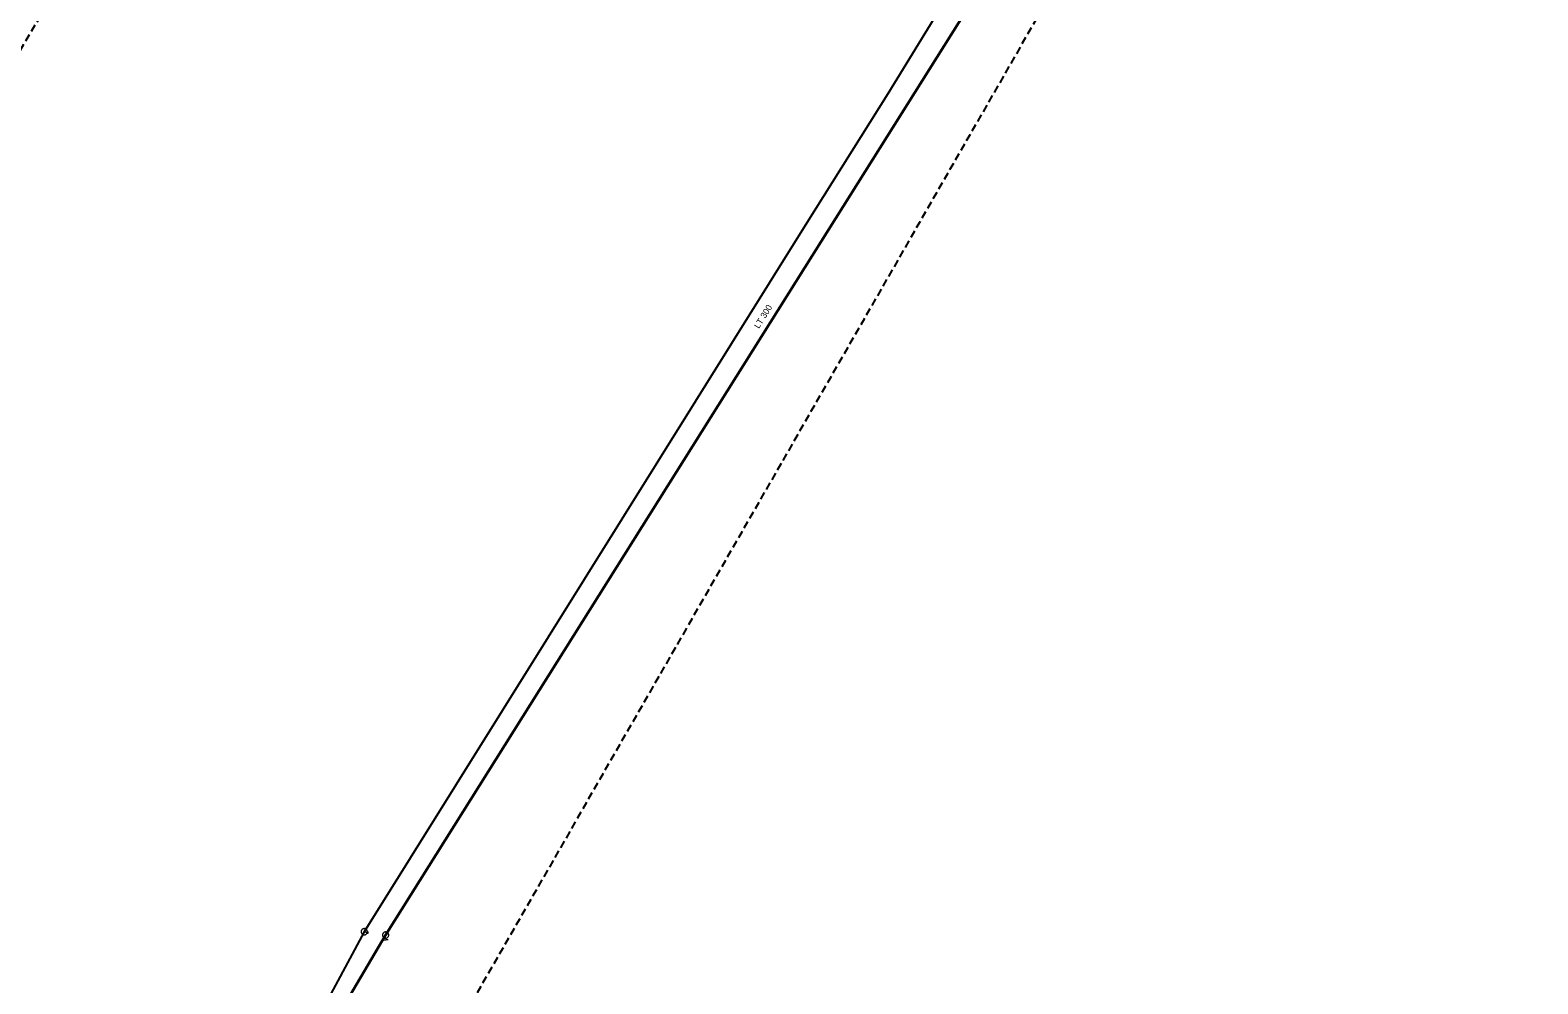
# Model space of a CAD drawing. Extents: x -724358 to -723714, y -973310 to -972026.
# Drawn here: x -724079.6 to -723836.6, y -972835.4 to -972681.7 of the extents above; entities that cross this region are included whole.
import ezdxf

# ---------------------------------------------------------------- set-up
doc = ezdxf.new("R2010")
doc.units = 0
doc.header["$LTSCALE"] = 0.4
doc.linetypes.add('MEDIUM_DASHED', pattern=[4.5, 3, -1.5])
for name, color, linetype, lineweight in [('1', 7, 'Continuous', 13), ('14', 7, 'Continuous', 13), ('17', 7, 'Continuous', 25), ('23', 7, 'Continuous', 13), ('47', 7, 'Continuous', 13), ('9', 7, 'Continuous', 13)]:
    doc.layers.add(name, color=color, linetype=linetype, lineweight=lineweight)

msp = doc.modelspace()

# ---------------------------------------------------------------- linework, layer by layer
at = {"layer": '1', "linetype": 'MEDIUM_DASHED', "lineweight": 25}
msp.add_lwpolyline([(-723809.944, -972026.35), (-723713.647, -972034.723), (-723734.581, -972361.295), (-724123.956, -973039.561), (-724241.187, -973309.611), (-724358.418, -973148.418), (-723860.186, -972315.24)], close=True, dxfattribs=at)
at = {"layer": '14'}
msp.add_line((-724025.8, -972827.022), (-724025.277, -972827.149), dxfattribs=at)
at = {"layer": '17', "lineweight": 35}
msp.add_line((-724070.768, -972909.289), (-724022.349, -972827.559), dxfattribs=at)
at = {"layer": '17'}
for points in [[(-723900.499, -972626.309), (-723922.64, -972661.32), (-723941.379, -972691.969), (-723954.71, -972713.199), (-723996.149, -972779.55), (-724025.8, -972827.022)], [(-724025.8, -972827.022), (-724033.14, -972840.629), (-724045.07, -972861.41), (-724063.359, -972892.16), (-724073.199, -972908.18)]]:
    msp.add_lwpolyline(points, dxfattribs=at)
at = {"layer": '17', "lineweight": 35}
msp.add_lwpolyline([(-724022.349, -972827.559), (-723952.142, -972715.728), (-723897.139, -972628.179)], dxfattribs=at)
at = {"layer": '23'}
for p in [(-724022.316, -972828.069), (-724022.639, -972828.37), (-724021.956, -972828.325)]:
    msp.add_line(p, (-724022.298, -972828.347), dxfattribs=at)
msp.add_lwpolyline([(-724022.844, -972827.587), (-724022.837, -972827.64), (-724022.828, -972827.691), (-724022.81, -972827.741), (-724022.788, -972827.787), (-724022.765, -972827.831), (-724022.732, -972827.874), (-724022.696, -972827.911), (-724022.658, -972827.947), (-724022.617, -972827.977), (-724022.57, -972828.001), (-724022.523, -972828.022), (-724022.474, -972828.037), (-724022.422, -972828.049), (-724022.371, -972828.055), (-724022.32, -972828.054), (-724022.269, -972828.048), (-724022.219, -972828.036), (-724022.169, -972828.02), (-724022.122, -972827.999), (-724022.076, -972827.972), (-724022.036, -972827.942), (-724021.996, -972827.907), (-724021.962, -972827.868), (-724021.932, -972827.824), (-724021.905, -972827.78), (-724021.884, -972827.734), (-724021.869, -972827.685), (-724021.858, -972827.633), (-724021.855, -972827.582), (-724021.852, -972827.527), (-724021.859, -972827.477), (-724021.871, -972827.426), (-724021.886, -972827.376), (-724021.908, -972827.33), (-724021.934, -972827.286), (-724021.964, -972827.243), (-724022, -972827.206), (-724022.038, -972827.17), (-724022.082, -972827.14), (-724022.126, -972827.115), (-724022.176, -972827.095), (-724022.225, -972827.077), (-724022.274, -972827.068), (-724022.328, -972827.063), (-724022.379, -972827.063), (-724022.43, -972827.069), (-724022.48, -972827.079), (-724022.53, -972827.097), (-724022.577, -972827.118), (-724022.623, -972827.145), (-724022.663, -972827.175), (-724022.703, -972827.211), (-724022.737, -972827.249), (-724022.767, -972827.29), (-724022.791, -972827.337), (-724022.815, -972827.383), (-724022.83, -972827.432), (-724022.838, -972827.484), (-724022.844, -972827.535)], close=True, dxfattribs=at)
at = {"layer": '47'}
for points in [[(-724025.3, -972827.022), (-724025.303, -972826.97), (-724025.311, -972826.918), (-724025.325, -972826.868), (-724025.343, -972826.819), (-724025.367, -972826.772), (-724025.396, -972826.728), (-724025.429, -972826.688), (-724025.466, -972826.651), (-724025.506, -972826.618), (-724025.55, -972826.589), (-724025.597, -972826.565), (-724025.646, -972826.547), (-724025.696, -972826.533), (-724025.748, -972826.525), (-724025.8, -972826.522), (-724025.852, -972826.525), (-724025.904, -972826.533), (-724025.955, -972826.547), (-724026.003, -972826.565), (-724026.05, -972826.589), (-724026.094, -972826.618), (-724026.135, -972826.651), (-724026.172, -972826.688), (-724026.205, -972826.728), (-724026.233, -972826.772), (-724026.257, -972826.819), (-724026.276, -972826.868), (-724026.289, -972826.918), (-724026.297, -972826.97), (-724026.3, -972827.022), (-724026.297, -972827.074), (-724026.289, -972827.126), (-724026.276, -972827.177), (-724026.257, -972827.225), (-724026.233, -972827.272), (-724026.205, -972827.316), (-724026.172, -972827.357), (-724026.135, -972827.394), (-724026.094, -972827.427), (-724026.05, -972827.455), (-724026.003, -972827.479), (-724025.955, -972827.498), (-724025.904, -972827.511), (-724025.852, -972827.519), (-724025.8, -972827.522), (-724025.748, -972827.519), (-724025.696, -972827.511), (-724025.646, -972827.498), (-724025.597, -972827.479), (-724025.55, -972827.455), (-724025.506, -972827.427), (-724025.466, -972827.394), (-724025.429, -972827.357), (-724025.396, -972827.316), (-724025.367, -972827.272), (-724025.343, -972827.225), (-724025.325, -972827.177), (-724025.311, -972827.126), (-724025.303, -972827.074)], [(-724025.718, -972827.022), (-724025.718, -972827.013), (-724025.72, -972827.005), (-724025.722, -972826.997), (-724025.725, -972826.989), (-724025.729, -972826.981), (-724025.734, -972826.974), (-724025.739, -972826.967), (-724025.745, -972826.961), (-724025.752, -972826.956), (-724025.759, -972826.951), (-724025.767, -972826.947), (-724025.775, -972826.944), (-724025.783, -972826.942), (-724025.791, -972826.94), (-724025.8, -972826.94), (-724025.809, -972826.94), (-724025.817, -972826.942), (-724025.825, -972826.944), (-724025.833, -972826.947), (-724025.841, -972826.951), (-724025.848, -972826.956), (-724025.855, -972826.961), (-724025.861, -972826.967), (-724025.867, -972826.974), (-724025.871, -972826.981), (-724025.875, -972826.989), (-724025.878, -972826.997), (-724025.88, -972827.005), (-724025.882, -972827.013), (-724025.882, -972827.022), (-724025.882, -972827.031), (-724025.88, -972827.039), (-724025.878, -972827.047), (-724025.875, -972827.055), (-724025.871, -972827.063), (-724025.867, -972827.07), (-724025.861, -972827.077), (-724025.855, -972827.083), (-724025.848, -972827.089), (-724025.841, -972827.093), (-724025.833, -972827.097), (-724025.825, -972827.1), (-724025.817, -972827.102), (-724025.809, -972827.104), (-724025.8, -972827.104), (-724025.791, -972827.104), (-724025.783, -972827.102), (-724025.775, -972827.1), (-724025.767, -972827.097), (-724025.759, -972827.093), (-724025.752, -972827.089), (-724025.745, -972827.083), (-724025.739, -972827.077), (-724025.734, -972827.07), (-724025.729, -972827.063), (-724025.725, -972827.055), (-724025.722, -972827.047), (-724025.72, -972827.039), (-724025.718, -972827.031)]]:
    msp.add_lwpolyline(points, close=True, dxfattribs=at)
at = {"layer": '9'}
for points in [[(-724025.403, -972827.149), (-724025.403, -972827.162), (-724025.401, -972827.175), (-724025.398, -972827.188), (-724025.393, -972827.2), (-724025.387, -972827.212), (-724025.38, -972827.223), (-724025.372, -972827.233), (-724025.362, -972827.243), (-724025.352, -972827.251), (-724025.341, -972827.258), (-724025.329, -972827.264), (-724025.317, -972827.269), (-724025.304, -972827.272), (-724025.291, -972827.274), (-724025.278, -972827.276), (-724025.265, -972827.275), (-724025.252, -972827.273), (-724025.239, -972827.27), (-724025.227, -972827.265), (-724025.215, -972827.259), (-724025.204, -972827.252), (-724025.194, -972827.244), (-724025.184, -972827.234), (-724025.176, -972827.224), (-724025.169, -972827.213), (-724025.163, -972827.201), (-724025.158, -972827.189), (-724025.155, -972827.176), (-724025.153, -972827.163), (-724025.151, -972827.15), (-724025.152, -972827.137), (-724025.154, -972827.124), (-724025.157, -972827.111), (-724025.162, -972827.099), (-724025.168, -972827.087), (-724025.175, -972827.076), (-724025.183, -972827.066), (-724025.193, -972827.056), (-724025.203, -972827.048), (-724025.214, -972827.041), (-724025.226, -972827.035), (-724025.238, -972827.03), (-724025.251, -972827.027), (-724025.264, -972827.025), (-724025.277, -972827.024), (-724025.29, -972827.024), (-724025.303, -972827.026), (-724025.316, -972827.029), (-724025.328, -972827.034), (-724025.34, -972827.04), (-724025.351, -972827.047), (-724025.361, -972827.055), (-724025.371, -972827.065), (-724025.379, -972827.075), (-724025.386, -972827.086), (-724025.392, -972827.098), (-724025.397, -972827.11), (-724025.4, -972827.123), (-724025.402, -972827.136)], [(-724025.383, -972827.149), (-724025.384, -972827.16), (-724025.382, -972827.171), (-724025.379, -972827.182), (-724025.375, -972827.192), (-724025.37, -972827.202), (-724025.364, -972827.211), (-724025.357, -972827.22), (-724025.349, -972827.228), (-724025.34, -972827.235), (-724025.331, -972827.241), (-724025.321, -972827.246), (-724025.311, -972827.25), (-724025.3, -972827.253), (-724025.289, -972827.256), (-724025.278, -972827.256), (-724025.267, -972827.256), (-724025.256, -972827.254), (-724025.245, -972827.251), (-724025.235, -972827.247), (-724025.225, -972827.242), (-724025.216, -972827.236), (-724025.207, -972827.229), (-724025.199, -972827.221), (-724025.192, -972827.212), (-724025.186, -972827.203), (-724025.181, -972827.193), (-724025.177, -972827.183), (-724025.174, -972827.172), (-724025.172, -972827.161), (-724025.171, -972827.15), (-724025.171, -972827.139), (-724025.173, -972827.128), (-724025.176, -972827.117), (-724025.18, -972827.107), (-724025.185, -972827.097), (-724025.191, -972827.088), (-724025.198, -972827.079), (-724025.206, -972827.071), (-724025.215, -972827.064), (-724025.224, -972827.058), (-724025.234, -972827.053), (-724025.244, -972827.049), (-724025.255, -972827.046), (-724025.266, -972827.044), (-724025.277, -972827.044), (-724025.288, -972827.043), (-724025.299, -972827.045), (-724025.31, -972827.048), (-724025.32, -972827.052), (-724025.33, -972827.057), (-724025.339, -972827.063), (-724025.348, -972827.07), (-724025.356, -972827.078), (-724025.363, -972827.087), (-724025.369, -972827.096), (-724025.374, -972827.106), (-724025.378, -972827.116), (-724025.381, -972827.127), (-724025.383, -972827.138)], [(-724025.364, -972827.149), (-724025.364, -972827.158), (-724025.363, -972827.167), (-724025.36, -972827.176), (-724025.357, -972827.184), (-724025.353, -972827.192), (-724025.348, -972827.2), (-724025.342, -972827.207), (-724025.336, -972827.213), (-724025.329, -972827.219), (-724025.321, -972827.224), (-724025.313, -972827.228), (-724025.305, -972827.231), (-724025.296, -972827.234), (-724025.287, -972827.235), (-724025.278, -972827.237), (-724025.269, -972827.236), (-724025.26, -972827.235), (-724025.251, -972827.232), (-724025.243, -972827.229), (-724025.235, -972827.225), (-724025.227, -972827.22), (-724025.22, -972827.214), (-724025.214, -972827.208), (-724025.208, -972827.201), (-724025.203, -972827.193), (-724025.199, -972827.185), (-724025.196, -972827.177), (-724025.193, -972827.168), (-724025.192, -972827.159), (-724025.19, -972827.15), (-724025.191, -972827.141), (-724025.192, -972827.132), (-724025.195, -972827.123), (-724025.198, -972827.115), (-724025.202, -972827.107), (-724025.207, -972827.099), (-724025.213, -972827.092), (-724025.219, -972827.086), (-724025.226, -972827.08), (-724025.234, -972827.075), (-724025.242, -972827.071), (-724025.25, -972827.068), (-724025.259, -972827.065), (-724025.268, -972827.064), (-724025.277, -972827.063), (-724025.286, -972827.063), (-724025.295, -972827.064), (-724025.304, -972827.067), (-724025.312, -972827.07), (-724025.32, -972827.074), (-724025.328, -972827.079), (-724025.335, -972827.085), (-724025.341, -972827.091), (-724025.347, -972827.098), (-724025.352, -972827.106), (-724025.356, -972827.114), (-724025.359, -972827.122), (-724025.362, -972827.131), (-724025.363, -972827.14)], [(-724025.344, -972827.149), (-724025.344, -972827.156), (-724025.343, -972827.163), (-724025.342, -972827.17), (-724025.339, -972827.176), (-724025.336, -972827.182), (-724025.332, -972827.188), (-724025.328, -972827.194), (-724025.323, -972827.199), (-724025.317, -972827.203), (-724025.311, -972827.207), (-724025.305, -972827.21), (-724025.299, -972827.213), (-724025.292, -972827.214), (-724025.285, -972827.217), (-724025.278, -972827.217), (-724025.271, -972827.217), (-724025.264, -972827.215), (-724025.257, -972827.214), (-724025.251, -972827.211), (-724025.244, -972827.208), (-724025.239, -972827.204), (-724025.233, -972827.2), (-724025.228, -972827.195), (-724025.224, -972827.189), (-724025.22, -972827.183), (-724025.217, -972827.177), (-724025.214, -972827.171), (-724025.212, -972827.164), (-724025.211, -972827.157), (-724025.21, -972827.15), (-724025.21, -972827.143), (-724025.211, -972827.136), (-724025.213, -972827.129), (-724025.216, -972827.123), (-724025.219, -972827.116), (-724025.223, -972827.111), (-724025.227, -972827.105), (-724025.232, -972827.1), (-724025.238, -972827.096), (-724025.243, -972827.092), (-724025.25, -972827.089), (-724025.256, -972827.086), (-724025.263, -972827.084), (-724025.27, -972827.083), (-724025.277, -972827.083), (-724025.284, -972827.083), (-724025.291, -972827.083), (-724025.298, -972827.085), (-724025.304, -972827.088), (-724025.31, -972827.091), (-724025.316, -972827.095), (-724025.322, -972827.099), (-724025.327, -972827.104), (-724025.331, -972827.11), (-724025.335, -972827.115), (-724025.338, -972827.122), (-724025.341, -972827.128), (-724025.342, -972827.135), (-724025.344, -972827.142)], [(-724025.324, -972827.149), (-724025.324, -972827.154), (-724025.324, -972827.159), (-724025.323, -972827.164), (-724025.321, -972827.168), (-724025.319, -972827.173), (-724025.316, -972827.177), (-724025.313, -972827.18), (-724025.309, -972827.184), (-724025.306, -972827.187), (-724025.302, -972827.19), (-724025.297, -972827.192), (-724025.293, -972827.194), (-724025.288, -972827.195), (-724025.283, -972827.197), (-724025.278, -972827.197), (-724025.273, -972827.197), (-724025.268, -972827.196), (-724025.263, -972827.195), (-724025.259, -972827.193), (-724025.254, -972827.191), (-724025.25, -972827.188), (-724025.246, -972827.185), (-724025.243, -972827.181), (-724025.24, -972827.178), (-724025.237, -972827.174), (-724025.235, -972827.169), (-724025.233, -972827.165), (-724025.232, -972827.16), (-724025.231, -972827.155), (-724025.23, -972827.15), (-724025.23, -972827.145), (-724025.231, -972827.14), (-724025.232, -972827.135), (-724025.234, -972827.131), (-724025.236, -972827.126), (-724025.239, -972827.122), (-724025.242, -972827.118), (-724025.245, -972827.115), (-724025.249, -972827.112), (-724025.253, -972827.109), (-724025.258, -972827.107), (-724025.262, -972827.105), (-724025.267, -972827.104), (-724025.272, -972827.103), (-724025.277, -972827.103), (-724025.282, -972827.103), (-724025.287, -972827.104), (-724025.292, -972827.104), (-724025.296, -972827.106), (-724025.301, -972827.108), (-724025.305, -972827.111), (-724025.308, -972827.114), (-724025.312, -972827.117), (-724025.315, -972827.121), (-724025.318, -972827.125), (-724025.32, -972827.13), (-724025.322, -972827.134), (-724025.323, -972827.139), (-724025.324, -972827.144)], [(-724025.304, -972827.149), (-724025.304, -972827.152), (-724025.305, -972827.155), (-724025.304, -972827.157), (-724025.303, -972827.16), (-724025.302, -972827.163), (-724025.3, -972827.165), (-724025.298, -972827.167), (-724025.296, -972827.169), (-724025.294, -972827.171), (-724025.292, -972827.173), (-724025.289, -972827.175), (-724025.286, -972827.176), (-724025.284, -972827.176), (-724025.281, -972827.177), (-724025.278, -972827.177), (-724025.275, -972827.177), (-724025.272, -972827.177), (-724025.269, -972827.176), (-724025.267, -972827.175), (-724025.264, -972827.174), (-724025.262, -972827.172), (-724025.259, -972827.17), (-724025.257, -972827.168), (-724025.256, -972827.166), (-724025.254, -972827.164), (-724025.253, -972827.161), (-724025.251, -972827.158), (-724025.251, -972827.156), (-724025.25, -972827.153), (-724025.249, -972827.15), (-724025.25, -972827.147), (-724025.25, -972827.144), (-724025.251, -972827.141), (-724025.252, -972827.139), (-724025.253, -972827.136), (-724025.255, -972827.134), (-724025.256, -972827.131), (-724025.258, -972827.129), (-724025.261, -972827.128), (-724025.263, -972827.126), (-724025.266, -972827.125), (-724025.268, -972827.124), (-724025.271, -972827.123), (-724025.274, -972827.123), (-724025.277, -972827.122), (-724025.28, -972827.123), (-724025.283, -972827.122), (-724025.285, -972827.124), (-724025.288, -972827.124), (-724025.291, -972827.125), (-724025.293, -972827.127), (-724025.295, -972827.128), (-724025.297, -972827.13), (-724025.299, -972827.133), (-724025.301, -972827.135), (-724025.302, -972827.138), (-724025.303, -972827.14), (-724025.304, -972827.143), (-724025.304, -972827.146)], [(-724025.285, -972827.149), (-724025.285, -972827.151), (-724025.285, -972827.151), (-724025.284, -972827.151), (-724025.284, -972827.153), (-724025.285, -972827.154), (-724025.283, -972827.154), (-724025.283, -972827.154), (-724025.283, -972827.156), (-724025.283, -972827.156), (-724025.282, -972827.157), (-724025.28, -972827.157), (-724025.28, -972827.157), (-724025.28, -972827.158), (-724025.278, -972827.158), (-724025.278, -972827.158), (-724025.277, -972827.158), (-724025.276, -972827.158), (-724025.276, -972827.157), (-724025.275, -972827.157), (-724025.273, -972827.157), (-724025.273, -972827.156), (-724025.273, -972827.156), (-724025.272, -972827.155), (-724025.272, -972827.155), (-724025.27, -972827.154), (-724025.27, -972827.153), (-724025.269, -972827.152), (-724025.269, -972827.152), (-724025.269, -972827.151), (-724025.269, -972827.15), (-724025.269, -972827.149), (-724025.269, -972827.148), (-724025.269, -972827.148), (-724025.27, -972827.147), (-724025.27, -972827.146), (-724025.271, -972827.145), (-724025.271, -972827.145), (-724025.272, -972827.144), (-724025.272, -972827.144), (-724025.273, -972827.143), (-724025.274, -972827.143), (-724025.275, -972827.142), (-724025.275, -972827.142), (-724025.276, -972827.142), (-724025.277, -972827.142), (-724025.278, -972827.142), (-724025.279, -972827.142), (-724025.279, -972827.142), (-724025.28, -972827.143), (-724025.281, -972827.142), (-724025.282, -972827.144), (-724025.282, -972827.144), (-724025.283, -972827.144), (-724025.283, -972827.144), (-724025.284, -972827.146), (-724025.284, -972827.147), (-724025.284, -972827.148), (-724025.285, -972827.148), (-724025.285, -972827.149)]]:
    msp.add_lwpolyline(points, close=True, dxfattribs=at)

# ---------------------------------------------------------------- texts
at = {"layer": '1'}
msp.add_text('LT 300', height=1, rotation=58, dxfattribs=at).set_placement((-723962.191, -972729.875))

doc.saveas('drawing.dxf')
